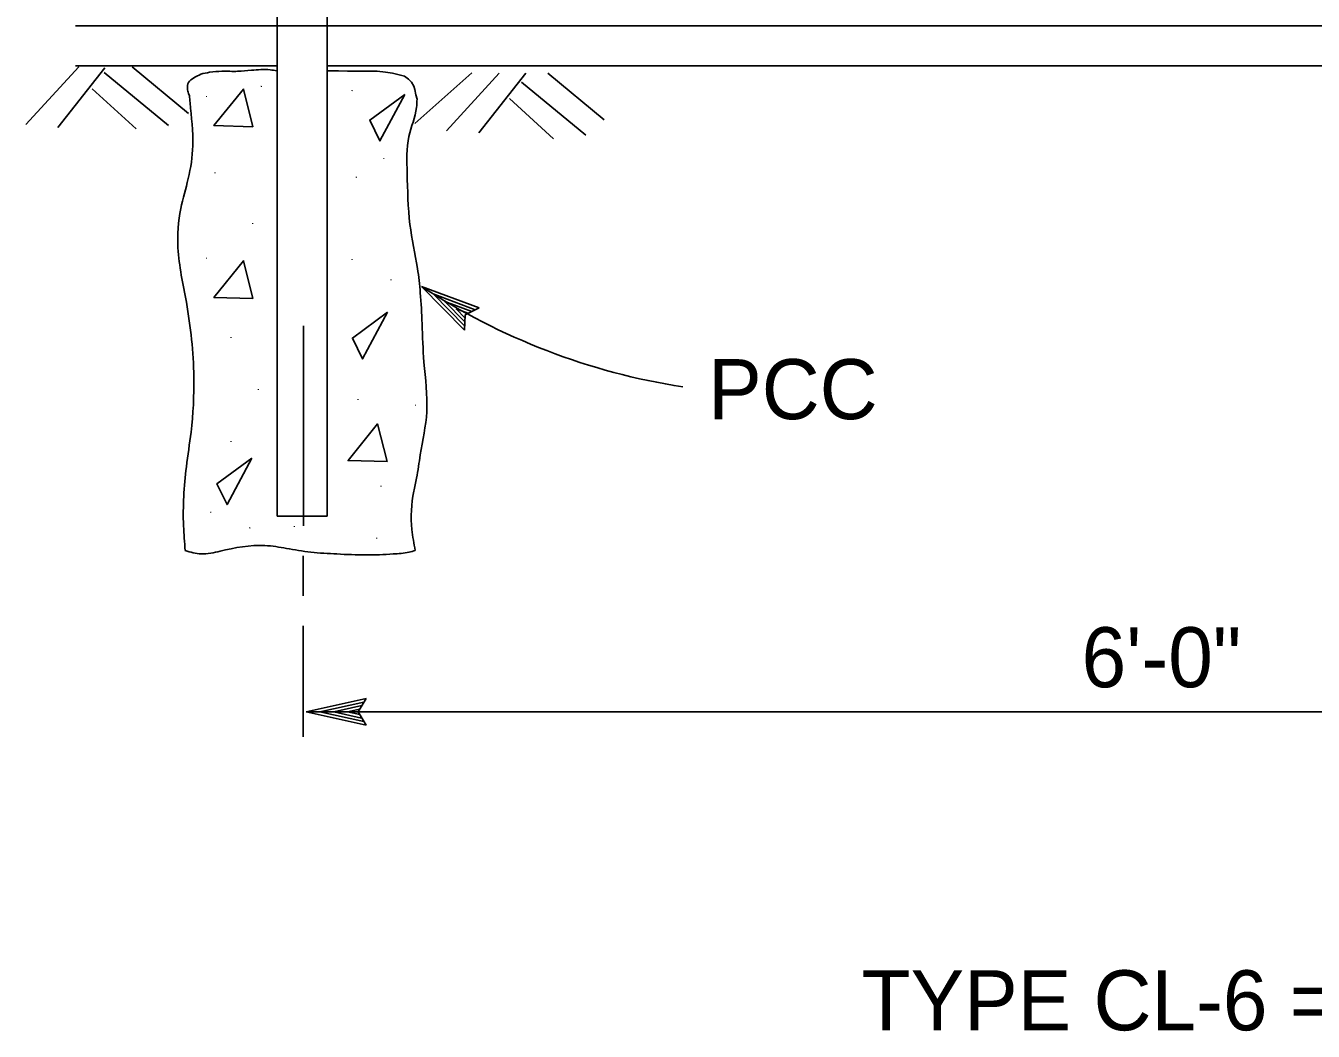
# Model space of a CAD drawing. Extents: x -121875 to -117742, y -103854 to -101122.
# Drawn here: x -121369.1 to -121240.4, y -102477.7 to -102377.2 of the extents above; entities that cross this region are included whole.
import ezdxf

# ---------------------------------------------------------------- set-up
doc = ezdxf.new("R2010")
doc.units = 0
for name, color, linetype in [('G-MARK', 7, 'Continuous'), ('G-TEXT', 7, 'Continuous'), ('Misc CnstDet(22)', 7, 'Continuous'), ('Nongeo Data(60)', 7, 'Continuous')]:
    doc.layers.add(name, color=color, linetype=linetype)

msp = doc.modelspace()

# ---------------------------------------------------------------- linework, layer by layer
at = {"layer": 'G-MARK'}
msp.add_line((-121341.08, -102445.78), (-121164.19, -102445.78), dxfattribs=at)
for points in [[(-121341.33, -102407.2), (-121341.35, -102427.2)], [(-121341.36, -102430.2), (-121341.36, -102434.2)], [(-121341.36, -102437.2), (-121341.37, -102448.28)]]:
    msp.add_lwpolyline(points, dxfattribs=at)
msp.add_arc((-121293.19, -102347.76), 66.35, 236.7837, 261.1414, dxfattribs=at)
at = {"layer": 'G-TEXT'}
for p, q in [((-121325.23, -102407.66), (-121329.53, -102403.27)), ((-121329.53, -102403.27), (-121329.53, -102403.27)), ((-121329.53, -102403.27), (-121323.78, -102405.42)), ((-121325.22, -102407.24), (-121328.37, -102404.02)), ((-121328.36, -102404.02), (-121324.17, -102405.6)), ((-121325.22, -102406.82), (-121327.22, -102404.77)), ((-121327.22, -102404.77), (-121324.51, -102405.79)), ((-121325.18, -102406.43), (-121326.06, -102405.53)), ((-121326.06, -102405.53), (-121324.9, -102405.96)), ((-121323.78, -102405.42), (-121325.17, -102406.1)), ((-121323.78, -102405.42), (-121323.78, -102405.42)), ((-121325.17, -102406.1), (-121325.23, -102407.66)), ((-121325.23, -102407.66), (-121325.23, -102407.66)), ((-121341.08, -102445.78), (-121335.08, -102444.45)), ((-121339.69, -102445.78), (-121335.31, -102444.81)), ((-121338.31, -102445.78), (-121335.49, -102445.16)), ((-121336.93, -102445.78), (-121335.72, -102445.52)), ((-121335.08, -102444.45), (-121335.88, -102445.78)), ((-121335.08, -102444.45), (-121335.08, -102444.45)), ((-121335.08, -102447.12), (-121341.08, -102445.78)), ((-121341.08, -102445.78), (-121341.08, -102445.78)), ((-121335.29, -102446.76), (-121339.7, -102445.78)), ((-121335.53, -102446.41), (-121338.31, -102445.78)), ((-121335.7, -102446.06), (-121336.93, -102445.78)), ((-121335.88, -102445.78), (-121335.08, -102447.12)), ((-121335.08, -102447.12), (-121335.08, -102447.12))]:
    msp.add_line(p, q, dxfattribs=at)
at = {"layer": 'Nongeo Data(60)'}
for p, q in [((-121343.97, -102426.24), (-121343.97, -102272.05)), ((-121338.97, -102426.24), (-121338.97, -102272.05)), ((-121343.97, -102426.24), (-121343.97, -102276.24)), ((-121337.33, -102377.24), (-121364.13, -102377.24)), ((-121161.97, -102377.24), (-121337.33, -102377.24)), ((-121343.97, -102381.24), (-121364.13, -102381.24)), ((-121166.97, -102381.24), (-121338.97, -102381.24)), ((-121363.81, -102381.32), (-121369.11, -102387.08)), ((-121361.2, -102381.43), (-121365.9, -102387.41)), ((-121361.28, -102381.89), (-121354.84, -102387.19)), ((-121358.46, -102381.34), (-121352.82, -102385.98)), ((-121337.85, -102381.73), (-121338.93, -102381.73)), ((-121336.92, -102381.78), (-121337.85, -102381.73)), ((-121335.79, -102381.78), (-121336.92, -102381.78)), ((-121333.98, -102381.78), (-121335.79, -102381.78)), ((-121333.14, -102381.88), (-121333.98, -102381.78)), ((-121332.45, -102381.98), (-121333.14, -102381.88)), ((-121331.23, -102382.27), (-121332.45, -102381.98)), ((-121330.83, -102382.57), (-121331.23, -102382.27)), ((-121324.5, -102381.92), (-121330.2, -102387)), ((-121321.76, -102381.96), (-121327.05, -102387.72)), ((-121319.09, -102381.96), (-121323.79, -102387.94)), ((-121316.9, -102381.98), (-121311.26, -102386.62)), ((-121362.46, -102383.54), (-121358.06, -102387.54)), ((-121330.54, -102382.86), (-121330.83, -102382.57)), ((-121330.29, -102383.25), (-121330.54, -102382.86)), ((-121330.19, -102383.6), (-121330.29, -102383.25)), ((-121330.1, -102384.14), (-121330.19, -102383.6)), ((-121319.55, -102382.86), (-121313.11, -102388.16)), ((-121329.98, -102384.57), (-121330.1, -102384.14)), ((-121320.73, -102384.51), (-121316.33, -102388.51)), ((-121338.97, -102426.24), (-121343.97, -102426.24))]:
    msp.add_line(p, q, dxfattribs=at)
for points in [[(-121346.39, -102387.32), (-121350.29, -102387.21), (-121347.33, -102383.55)], [(-121331.22, -102384.08), (-121333.69, -102388.73), (-121334.71, -102386.65)], [(-121346.39, -102404.48), (-121350.29, -102404.37), (-121347.33, -102400.71)], [(-121332.95, -102405.85), (-121335.42, -102410.51), (-121336.44, -102408.43)], [(-121332.98, -102420.78), (-121336.88, -102420.67), (-121333.93, -102417.01)], [(-121346.5, -102420.42), (-121348.97, -102425.07), (-121349.99, -102423)]]:
    msp.add_lwpolyline(points, close=True, dxfattribs=at)
for points in [[(-121352.75, -102384.18), (-121352.83, -102383.99), (-121352.93, -102383.5), (-121352.83, -102382.91), (-121352.29, -102382.42), (-121351.6, -102382.08), (-121350.72, -102381.88), (-121349.49, -102381.78), (-121347.92, -102381.78), (-121346.55, -102381.68), (-121344.68, -102381.63), (-121343.99, -102381.73)], [(-121352.75, -102384.18), (-121352.68, -102384.92), (-121352.4, -102389.22), (-121352.86, -102392.5), (-121353.61, -102395.49), (-121353.89, -102399.42), (-121353.05, -102404.85), (-121352.3, -102412.33), (-121352.58, -102417.85), (-121353.05, -102421.31), (-121353.33, -102427.21), (-121353.16, -102429.66)], [(-121330.16, -102429.66), (-121330.5, -102427.58), (-121330.32, -102423.75), (-121330.04, -102422.44), (-121329.66, -102420.1), (-121329.01, -102415.79), (-121329.29, -102410.84), (-121329.48, -102407), (-121329.66, -102403.91), (-121329.94, -102401.48), (-121330.69, -102397.08), (-121330.97, -102391.94), (-121330.79, -102388.29), (-121330.04, -102385.39), (-121329.98, -102384.57)], [(-121353.16, -102429.66), (-121351.55, -102430.01), (-121349.68, -102429.73), (-121345.19, -102429.17), (-121343.04, -102429.45), (-121340.61, -102429.83), (-121337.99, -102430.01), (-121335.09, -102430.11), (-121332.38, -102430.01), (-121330.79, -102429.83), (-121330.16, -102429.66)]]:
    msp.add_spline(points, degree=3, dxfattribs=at)

# ---------------------------------------------------------------- texts
at = {"layer": 'Misc CnstDet(22)'}
msp.add_text('TYPE CL-6 = 6\'-0" FABRIC', height=6, dxfattribs=at).set_placement((-121285.53, -102477.61))
at = {"layer": 'Nongeo Data(60)'}
for p in [(-121345.61, -102383.13), (-121336.53, -102383.56), (-121351.09, -102384.14), (-121333.36, -102390.34), (-121350.23, -102391.78), (-121336.1, -102392.22), (-121346.48, -102396.83), (-121351.09, -102400.29), (-121336.53, -102400.44), (-121332.64, -102402.46), (-121348.64, -102408.22), (-121345.9, -102413.42), (-121335.95, -102414.43), (-121330.19, -102415), (-121348.64, -102418.61), (-121333.65, -102423.08), (-121350.66, -102425.67), (-121346.77, -102427.26), (-121342.3, -102427.12), (-121334.08, -102428.27)]:
    msp.add_text('.', height=0.8, rotation=266.9315, dxfattribs=at).set_placement(p)
for s, p in [('PCC', (-121300.87, -102416.54)), ('6\'-0"', (-121263.54, -102443.33))]:
    msp.add_text(s, height=6, dxfattribs=at).set_placement(p)

doc.saveas('drawing.dxf')
